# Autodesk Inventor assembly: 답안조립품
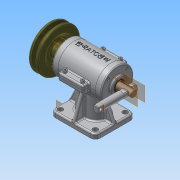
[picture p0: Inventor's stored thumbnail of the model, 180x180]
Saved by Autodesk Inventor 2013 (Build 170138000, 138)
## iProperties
Created: 2015-05
Part Number: 답안조립품
Document SubType Name: Assembly
Designer: Administrator
Mass: 1947.44 g
Surface Area: 1472.71 cm^2
Volume: 477.362 cm^3
Density: 4.07959 g/cm^3
Author: Administrator
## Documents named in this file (18)
- C:\Users\Administrator\Desktop\350508V1051\답안조립품.iam
- C:\Users\Administrator\Desktop\350508V1051\M3x0.5x8.ipt
- C:\Users\Administrator\Desktop\350508V1051\M4x0.5x14.ipt
- C:\Users\Administrator\Desktop\350508V1051\V-벨트풀리.ipt
- C:\Users\Administrator\Desktop\350508V1051\가변스프링.ipt
- C:\Users\Administrator\Desktop\350508V1051\너트 M8.ipt
- C:\Users\Administrator\Desktop\350508V1051\뒤커버.ipt
- C:\Users\Administrator\Desktop\350508V1051\링크.ipt
- C:\Users\Administrator\Desktop\350508V1051\멈춤나사.ipt
- C:\Users\Administrator\Desktop\350508V1051\베어링 6201.ipt
- C:\Users\Administrator\Desktop\350508V1051\베어링 6202.ipt
- C:\Users\Administrator\Desktop\350508V1051\본체 커버.ipt
- C:\Users\Administrator\Desktop\350508V1051\본체.ipt
- C:\Users\Administrator\Desktop\350508V1051\슬라이드.ipt
- C:\Users\Administrator\Desktop\350508V1051\앞커버.ipt
- C:\Users\Administrator\Desktop\350508V1051\오일실.ipt
- C:\Users\Administrator\Desktop\350508V1051\키4x4.ipt
- C:\Users\Administrator\Desktop\350508V1051\편심축.ipt
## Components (15 placed, 5 different names)
1. 가변스프링:1
2. V-벨트풀리:1 — 플러쉬:1
3. M4x0.5x14:1
4. KS B 1012 C - 미터 C M8:1
5. M4x0.5x14:2
6. M4x0.5x14:3
7. M4x0.5x14:4
8. M3x0.5x8:2
9. M3x0.5x8:3
10. M3x0.5x8:4
11. M3x0.5x8:5
12. M3x0.5x8:1
13. M3x0.5x8:6
14. M3x0.5x8:7
15. M3x0.5x8:8
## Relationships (1: Flush 1)
- 플러쉬:1 [Flush]: V-벨트풀리:1
